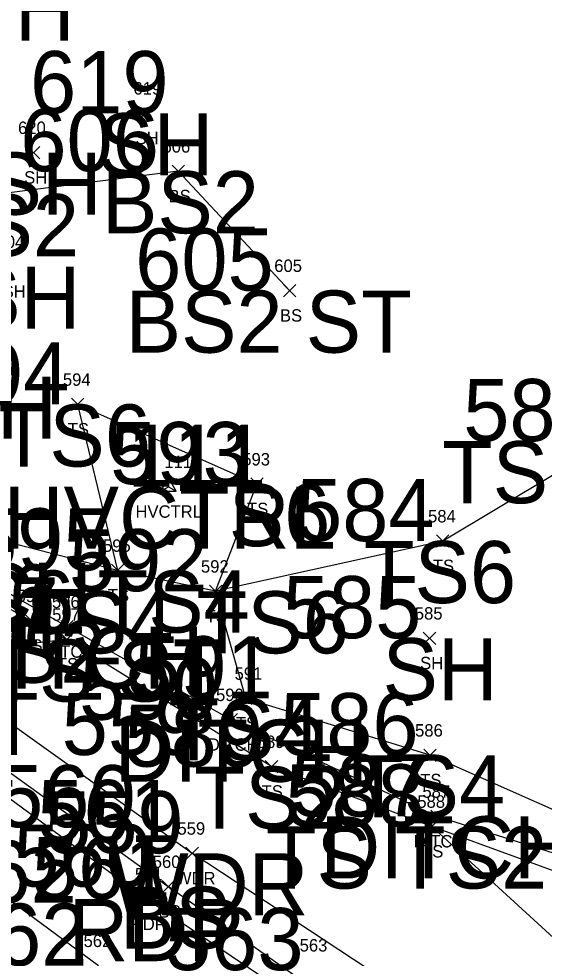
# Model space of a CAD drawing. Extents: x 1616840 to 1618410, y 488554 to 491945.
# Drawn here: x 1618151.6 to 1618236.2, y 488744.1 to 488895.3 of the extents above; entities that cross this region are included whole.
import ezdxf

# ---------------------------------------------------------------- set-up
doc = ezdxf.new("R2010")
doc.units = 0
for name, color, linetype in [('C_A', 7, 'Continuous'), ('C_I', 7, 'Continuous'), ('CPSM', 7, 'Continuous'), ('D_A', 7, 'Continuous'), ('D_I', 7, 'Continuous'), ('D_TIC', 7, 'Continuous'), ('DD', 7, 'Continuous'), ('L_A', 7, 'Continuous'), ('L_I', 7, 'Continuous'), ('L_TIC', 7, 'Continuous'), ('LAWA', 7, 'Continuous'), ('LELB', 7, 'Continuous'), ('P_A', 7, 'Continuous'), ('P_I', 7, 'Continuous'), ('P_TIC', 7, 'Continuous'), ('PET', 7, 'Continuous'), ('PRC', 7, 'Continuous'), ('S_I', 7, 'Continuous')]:
    doc.layers.add(name, color=color, linetype=linetype)

msp = doc.modelspace()

# ---------------------------------------------------------------- linework, layer by layer
at = {"layer": 'CPSM'}
for p, q in [((1618174.42, 488819.27), (1618175.67, 488821.43)), ((1618176.92, 488819.27), (1618175.67, 488821.43)), ((1618175.67, 488819.99), (1618175.67, 488821.43)), ((1618174.42, 488819.27), (1618175.67, 488819.99)), ((1618174.42, 488819.27), (1618176.92, 488819.27)), ((1618175.67, 488819.99), (1618175.67, 488819.99)), ((1618175.67, 488819.99), (1618176.92, 488819.27))]:
    msp.add_line(p, q, dxfattribs=at)
at = {"layer": 'D_TIC'}
for points in [[(1618158.33, 488796.45), (1618160.33, 488798.45)], [(1618160.33, 488796.45), (1618158.33, 488798.45)], [(1618184.78, 488781.47), (1618186.78, 488783.47)], [(1618186.78, 488781.47), (1618184.78, 488783.47)], [(1618217.93, 488765.9), (1618219.93, 488767.9)], [(1618219.93, 488765.9), (1618217.93, 488767.9)]]:
    msp.add_lwpolyline(points, dxfattribs=at)
at = {"layer": 'DD'}
msp.add_lwpolyline([(1618334.32, 488725.5), (1618306.17, 488735.78), (1618260.33, 488753.83), (1618218.93, 488766.9), (1618185.78, 488782.47), (1618159.33, 488797.45), (1618141.33, 488807.73), (1618125.06, 488820.25), (1618102.03, 488843.81)], dxfattribs=at)
msp.add_lwpolyline([(1618334.32, 488725.5), (1618306.17, 488735.78), (1618260.33, 488753.83), (1618218.93, 488766.9), (1618185.78, 488782.47), (1618159.33, 488797.45), (1618141.33, 488807.73), (1618125.06, 488820.25), (1618102.03, 488843.81)], dxfattribs=at)
at = {"layer": 'L_TIC'}
for points in [[(1618170.88, 488879.14), (1618172.88, 488881.14)], [(1618172.88, 488879.14), (1618170.88, 488881.14)], [(1618152.94, 488872.79), (1618154.94, 488874.79)], [(1618154.94, 488872.79), (1618152.94, 488874.79)], [(1618176.25, 488869.79), (1618178.25, 488871.79)], [(1618178.25, 488869.79), (1618176.25, 488871.79)], [(1618194.19, 488850.57), (1618196.19, 488852.57)], [(1618196.19, 488850.57), (1618194.19, 488852.57)], [(1618160.04, 488832.24), (1618162.04, 488834.24)], [(1618162.04, 488832.24), (1618160.04, 488834.24)], [(1618188.92, 488819.41), (1618190.92, 488821.41)], [(1618190.92, 488819.41), (1618188.92, 488821.41)], [(1618218.84, 488810.24), (1618220.84, 488812.24)], [(1618220.84, 488810.24), (1618218.84, 488812.24)], [(1618166.49, 488805.5), (1618168.49, 488807.5)], [(1618168.49, 488805.5), (1618166.49, 488807.5)], [(1618166.49, 488805.5), (1618168.49, 488807.5)], [(1618168.49, 488805.5), (1618166.49, 488807.5)], [(1618182.26, 488802.15), (1618184.26, 488804.15)], [(1618184.26, 488802.15), (1618182.26, 488804.15)], [(1618182.26, 488802.15), (1618184.26, 488804.15)], [(1618184.26, 488802.15), (1618182.26, 488804.15)], [(1618152.57, 488797.41), (1618154.57, 488799.41)], [(1618154.57, 488797.41), (1618152.57, 488799.41)], [(1618158.3, 488794.39), (1618160.3, 488796.39)], [(1618160.3, 488794.39), (1618158.3, 488796.39)], [(1618158.3, 488794.39), (1618160.3, 488796.39)], [(1618160.3, 488794.39), (1618158.3, 488796.39)], [(1618216.71, 488794.59), (1618218.71, 488796.59)], [(1618218.71, 488794.59), (1618216.71, 488796.59)], [(1618187.12, 488784.9), (1618189.12, 488786.9)], [(1618189.12, 488784.9), (1618187.12, 488786.9)], [(1618216.81, 488775.75), (1618218.81, 488777.75)], [(1618218.81, 488775.75), (1618216.81, 488777.75)], [(1618191.27, 488773.91), (1618193.27, 488775.91)], [(1618193.27, 488773.91), (1618191.27, 488775.91)], [(1618217.11, 488764.28), (1618219.11, 488766.28)], [(1618219.11, 488764.28), (1618217.11, 488766.28)], [(1618217.11, 488764.28), (1618219.11, 488766.28)], [(1618219.11, 488764.28), (1618217.11, 488766.28)], [(1618178.49, 488759.95), (1618180.49, 488761.95)], [(1618180.49, 488759.95), (1618178.49, 488761.95)], [(1618174.64, 488754.59), (1618176.64, 488756.59)], [(1618176.64, 488754.59), (1618174.64, 488756.59)]]:
    msp.add_lwpolyline(points, dxfattribs=at)
at = {"layer": 'LAWA'}
for points in [[(1618143.29, 488786.79), (1618179.49, 488760.95)], [(1618143.29, 488786.79), (1618179.49, 488760.95)], [(1618385.56, 488648.27), (1618346.37, 488665.17), (1618297.28, 488687.5), (1618273.77, 488699.31), (1618221.98, 488732.96), (1618179.49, 488760.95)], [(1618385.56, 488648.27), (1618346.37, 488665.17), (1618297.28, 488687.5), (1618273.77, 488699.31), (1618221.98, 488732.96), (1618179.49, 488760.95)]]:
    msp.add_lwpolyline(points, dxfattribs=at)
at = {"layer": 'LELB'}
for points in [[(1618195.19, 488851.57), (1618177.25, 488870.79), (1618148.29, 488867.11), (1618138.49, 488883.52)], [(1618195.19, 488851.57), (1618177.25, 488870.79), (1618148.29, 488867.11), (1618138.49, 488883.52)], [(1618335.13, 488729.22), (1618289.86, 488745.7), (1618261.22, 488757.46), (1618217.81, 488776.75), (1618188.12, 488785.9), (1618183.26, 488803.15), (1618167.49, 488806.5), (1618138.61, 488813.88), (1618120.24, 488832.87), (1618101.99, 488848.67), (1618101.83, 488860.48), (1618116.51, 488870.01)], [(1618335.13, 488729.22), (1618289.86, 488745.7), (1618261.22, 488757.46), (1618217.81, 488776.75), (1618188.12, 488785.9), (1618183.26, 488803.15), (1618167.49, 488806.5), (1618138.61, 488813.88), (1618120.24, 488832.87), (1618101.99, 488848.67), (1618101.83, 488860.48), (1618116.51, 488870.01)], [(1618330.66, 488723.42), (1618291.12, 488738.04), (1618260.44, 488749.79), (1618218.11, 488765.28), (1618192.27, 488774.91), (1618159.3, 488795.39), (1618153.57, 488798.41), (1618138.2, 488806.83), (1618124.27, 488818.44), (1618107.6, 488832.68), (1618102.03, 488843.81)], [(1618330.66, 488723.42), (1618291.12, 488738.04), (1618260.44, 488749.79), (1618218.11, 488765.28), (1618192.27, 488774.91), (1618159.3, 488795.39), (1618153.57, 488798.41), (1618138.2, 488806.83), (1618124.27, 488818.44), (1618107.6, 488832.68), (1618102.03, 488843.81)], [(1618246.77, 488827.33), (1618219.84, 488811.24), (1618183.26, 488803.15), (1618189.92, 488820.41), (1618161.04, 488833.24), (1618167.49, 488806.5)], [(1618246.77, 488827.33), (1618219.84, 488811.24), (1618183.26, 488803.15), (1618189.92, 488820.41), (1618161.04, 488833.24), (1618167.49, 488806.5)], [(1618159.3, 488795.39), (1618139.73, 488793.15), (1618132.98, 488801.23)], [(1618159.3, 488795.39), (1618139.73, 488793.15), (1618132.98, 488801.23)], [(1618148.46, 488775.15), (1618175.64, 488755.59)], [(1618148.46, 488775.15), (1618175.64, 488755.59)], [(1618372.73, 488669.19), (1618328.1, 488689.57), (1618302.14, 488707.09), (1618254.13, 488732.3), (1618218.11, 488765.28)], [(1618372.73, 488669.19), (1618328.1, 488689.57), (1618302.14, 488707.09), (1618254.13, 488732.3), (1618218.11, 488765.28)], [(1618382.99, 488642.15), (1618341.81, 488658.6), (1618297.33, 488678.13), (1618265.34, 488694.6), (1618228.02, 488718.67), (1618175.64, 488755.59)], [(1618382.99, 488642.15), (1618341.81, 488658.6), (1618297.33, 488678.13), (1618265.34, 488694.6), (1618228.02, 488718.67), (1618175.64, 488755.59)]]:
    msp.add_lwpolyline(points, dxfattribs=at)
at = {"layer": 'P_TIC'}
for points in [[(1618171.11, 488752.58), (1618173.11, 488754.58)], [(1618173.11, 488752.58), (1618171.11, 488754.58)]]:
    msp.add_lwpolyline(points, dxfattribs=at)
at = {"layer": 'PET'}
for points in [[(1618146.01, 488772.77), (1618172.11, 488753.58)], [(1618146.01, 488772.77), (1618172.11, 488753.58)], [(1618381.59, 488639.33), (1618338.75, 488657.04), (1618296.81, 488677.29), (1618262.28, 488695.58), (1618226.85, 488716.74), (1618172.11, 488753.58)], [(1618381.59, 488639.33), (1618338.75, 488657.04), (1618296.81, 488677.29), (1618262.28, 488695.58), (1618226.85, 488716.74), (1618172.11, 488753.58)]]:
    msp.add_lwpolyline(points, dxfattribs=at)
at = {"layer": 'PRC'}
msp.add_lwpolyline([(1618137.08, 488762.99), (1618164.41, 488742.86)], dxfattribs=at)
msp.add_lwpolyline([(1618137.08, 488762.99), (1618164.41, 488742.86)], dxfattribs=at)

# ---------------------------------------------------------------- texts
at = {"layer": 'C_A'}
for s, height, p in [('SH', 10, (1618142, 488891.81)), ('SH', 10, (1618164.32, 488870.14)), ('SH', 10, (1618146.38, 488863.79)), ('BS2', 10, (1618164.97, 488860.79)), ('BS2', 10, (1618136, 488857.11)), ('SH', 10, (1618142.92, 488845.43)), ('BS2 ST', 10, (1618168.78, 488841.57)), ('SH', 10, (1618139.14, 488827.71)), ('TS6', 10, (1618148.32, 488823.24)), ('TS6 ST', 10, (1618219.72, 488817.33)), ('HVCTRL', 10, (1618149.13, 488809.99)), ('TS6', 10, (1618177.21, 488810.41)), ('HVCTRL', 2, (1618170.36, 488814.99)), ('TS6', 10, (1618207.13, 488801.24)), ('DITCH', 10, (1618122.51, 488797.73)), ('TS6 TS4', 10, (1618136, 488796.5)), ('TS4 TS6', 10, (1618151.96, 488793.15)), ('TS2', 10, (1618141.13, 488788.41)), ('DITCH', 10, (1618140.51, 488787.45)), ('TS2 TS ST', 10, (1618118.4, 488785.39)), ('SH', 10, (1618210.15, 488785.59)), ('WDL10 JT 559', 10, (1618091.6, 488776.79)), ('TS4', 10, (1618175.68, 488775.9)), ('DITCH', 10, (1618166.96, 488772.47)), ('TS4', 10, (1618205.37, 488766.75)), ('BS JT 560', 10, (1618107.95, 488765.15)), ('TS2', 10, (1618179.83, 488764.91)), ('RDP JT 561', 10, (1618104.04, 488762.77)), ('DITCH', 10, (1618200.11, 488756.9)), ('TS TS2', 10, (1618191.34, 488755.28)), ('CR JT 562', 10, (1618097, 488752.99)), ('WDR', 10, (1618166.3, 488750.95)), ('BS', 10, (1618167.84, 488745.59)), ('RDP', 10, (1618159.55, 488743.58))]:
    msp.add_text(s, height=height, dxfattribs=at).set_placement(p)
at = {"layer": 'C_I'}
for s, height, p in [('619', 10, (1618153.38, 488880.14)), ('606', 10, (1618151.82, 488870.79)), ('605', 10, (1618170.31, 488851.57)), ('594', 10, (1618137.41, 488833.24)), ('583', 10, (1618223.14, 488827.33)), ('593', 10, (1618166.3, 488820.41)), ('111', 10, (1618169.05, 488819.99)), ('111', 2, (1618175.01, 488822.99)), ('584', 10, (1618196.22, 488811.24)), ('595', 10, (1618143.87, 488806.5)), ('592', 10, (1618159.64, 488803.15)), ('596', 10, (1618135.15, 488797.45)), ('597', 10, (1618135.68, 488795.39)), ('585', 10, (1618194.09, 488795.59)), ('591', 10, (1618170.17, 488785.9)), ('590', 10, (1618161.29, 488782.47)), ('586', 10, (1618193.64, 488776.75)), ('589', 10, (1618168.57, 488774.91)), ('587', 10, (1618195.31, 488766.9)), ('588', 10, (1618194.49, 488765.28)), ('559', 10, (1618155.79, 488760.95)), ('560', 10, (1618150.68, 488755.59)), ('561', 10, (1618153.69, 488753.58)), ('562', 10, (1618140.31, 488742.86)), ('563', 10, (1618175.12, 488742.14))]:
    msp.add_text(s, height=height, dxfattribs=at).set_placement(p)
at = {"layer": 'D_A'}
for p in [(1618155.56, 488792.45), (1618182.01, 488777.47), (1618215.17, 488761.9)]:
    msp.add_text('DITCH', height=2, dxfattribs=at).set_placement(p)
at = {"layer": 'D_I'}
for s, p in [('596', (1618156.91, 488800.45)), ('590', (1618183.33, 488785.47)), ('587', (1618216.57, 488769.9))]:
    msp.add_text(s, height=2, dxfattribs=at).set_placement(p)
at = {"layer": 'L_A'}
for s, p in [('SH', (1618170.37, 488875.14)), ('SH', (1618152.43, 488868.79)), ('BS', (1618175.69, 488865.79)), ('SH', (1618148.97, 488850.43)), ('BS', (1618193.63, 488846.57)), ('TS', (1618159.45, 488828.24)), ('TS', (1618188.33, 488815.41)), ('TS', (1618218.25, 488806.24)), ('TS', (1618165.9, 488801.5)), ('TS', (1618165.9, 488801.5)), ('TS', (1618181.67, 488798.15)), ('TS', (1618181.67, 488798.15)), ('TS', (1618151.98, 488793.41)), ('TS', (1618157.71, 488790.39)), ('TS', (1618157.71, 488790.39)), ('SH', (1618216.2, 488790.59)), ('TS', (1618186.53, 488780.9)), ('TS', (1618216.22, 488771.75)), ('TS', (1618190.68, 488769.91)), ('TS', (1618216.52, 488760.28)), ('TS', (1618216.52, 488760.28)), ('WDR', (1618176.86, 488755.95)), ('BS', (1618174.08, 488750.59))]:
    msp.add_text(s, height=2, dxfattribs=at).set_placement(p)
at = {"layer": 'L_I'}
for s, p in [('619', (1618170.03, 488883.14)), ('620', (1618151.45, 488876.79)), ('606', (1618174.71, 488873.79)), ('604', (1618147.99, 488858.43)), ('605', (1618192.71, 488854.57)), ('594', (1618158.67, 488836.24)), ('593', (1618187.56, 488823.41)), ('584', (1618217.48, 488814.24)), ('595', (1618165.13, 488809.5)), ('595', (1618165.13, 488809.5)), ('592', (1618180.9, 488806.15)), ('592', (1618180.9, 488806.15)), ('599', (1618151.2, 488801.41)), ('597', (1618156.94, 488798.39)), ('597', (1618156.94, 488798.39)), ('585', (1618215.35, 488798.59)), ('591', (1618186.32, 488788.9)), ('586', (1618215.39, 488779.75)), ('589', (1618189.9, 488777.91)), ('588', (1618215.75, 488768.28)), ('588', (1618215.75, 488768.28)), ('559', (1618177.12, 488763.95)), ('560', (1618173.14, 488758.59))]:
    msp.add_text(s, height=2, dxfattribs=at).set_placement(p)
at = {"layer": 'P_A'}
msp.add_text('RDP', height=2, dxfattribs=at).set_placement((1618169.6, 488748.58))
at = {"layer": 'P_I'}
for s, p in [('561', (1618170.27, 488756.58)), ('562', (1618162, 488745.86))]:
    msp.add_text(s, height=2, dxfattribs=at).set_placement(p)
at = {"layer": 'S_I'}
msp.add_text('563', height=2, dxfattribs=at).set_placement((1618196.8, 488745.14))

doc.saveas('drawing.dxf')
